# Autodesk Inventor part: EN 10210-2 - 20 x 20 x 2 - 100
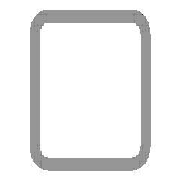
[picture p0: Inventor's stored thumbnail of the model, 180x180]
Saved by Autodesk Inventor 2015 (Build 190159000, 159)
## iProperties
Created: 2015-05
Part Number: EN 10210-2 - 20 x 20 x 2 - 100
Material: Steel, Mild
Description: Tube
Document SubType Name: Modeling
Standard: DIN
Designer: TREINA6
Standard Revision: 1997
Standards Organization: DIN
Language: en-US
Size Designation: 20 x 20 x 2
Categories: <MemberInstance><Categories><Category DisplayName="Structural Shapes" InternalName="089c4875-fa83-4c05-b084-43b9cc11f5ed" Mnemonic="GRDR"><CategoryParameter Dis
Stock Number: 20 x 20 x 2
Density: 7.85 g/cm^3
Appearance: Semi-Polished
IsCustomPart: 1
G_L: 100,000 mm
G_W: 20,000 mm
G_H: 20,000 mm
_CCFamilyMember: 1
_CCFamilyDisplayName: DIN EN 10210-2 (Square) - Tube
_FrameMemberDoc: Frame Member File
_Version: 15.0.0
_GetPNFromCC: 1
Author: TREINA6
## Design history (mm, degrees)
node "Start plane"
node "End plane"
sketch "Sketch"
  geometry: L1 (-10, -7)-(-10, 7); L2 (-7, 10)-(7, 10); L3 (10, 7)-(10, -7); L4 (7, -10)-(-7, -10); L5 (-7, 8)-(7, 8); L6 (8, 7)-(8, -7); L7 (7, -8)-(-7, -8); L8 (-8, -7)-(-8, 7); L9 (0, 14.87)-(0, -14.87) reference; L10 (-14.87, 0)-(14.87, 0) reference; A1 r 3 centre (-7, -7) between (-10, -7) and (-7, -10); A2 r 3 centre (-7, 7) between (-7, 10) and (-10, 7); A3 r 3 centre (7, 7) between (10, 7) and (7, 10); A4 r 3 centre (7, -7) between (7, -10) and (10, -7); A5 r 1 centre (-7, 7) between (-7, 8) and (-8, 7); A6 r 1 centre (7, 7) between (8, 7) and (7, 8); A7 r 1 centre (7, -7) between (7, -8) and (8, -7); A8 r 1 centre (-7, -7) between (-8, -7) and (-7, -8)
  constraints: 16 end point, 16 point on circle, 8 centre point, 8 tangent, 4 parallel, 3 equal radius, 2 perpendicular, 7 other
  dimensions: "d7" = 3 radius of A1 (= G_IR); "d10" = 20 distance between parallel lines of L2 L4 (= G_H); "d11" = 20 distance between parallel lines of L1 L3 (= G_W); "d12" = 2 distance between parallel lines of L3 L6 (= G_T); "d15" = 10 distance between parallel lines of L2 L10 (= 0.5 x d10); "d16" = 10 distance between parallel lines of L9 L3 (= 0.5 x d11)
extrude "Body" new body sketch "Sketch" stored distance "d3" = 100 (= G_L); taper "d4" = 0 deg
node "Driven Length"
  sketch "Sketch3"
    geometry: L1 (0, 0)-(10, 0) reference
    constraints: 2 end point, 1 horizontal
  workplane "Work Plane3"
  sketch "Sketch4"
    geometry: L1 (-2, 0)-(12, 0) reference; L2 (-2, 100)-(12, 100) reference
    dimensions: "d18" = 100 distance between parallel lines of L1 L2 (derived)
body "Solid1"
other parameters: "G_W" = 20 [user parameter; used in 1 equation term], "G_H" = 20 [user parameter; used in 1 equation term], "G_T" = 2 [user parameter; used in 1 equation term], "G_IR" = 3 [user parameter; used in 1 equation term], "G_L" = 100 (= d18) [user parameter; used in 1 equation term], "G_OFFSET_START" = 0 [user parameter; used in 1 equation term], "G_OFFSET_END" = 0 [user parameter; used in 1 equation term], "d13" = 0 (computed from G_OFFSET_START), "d17" = 90 deg
